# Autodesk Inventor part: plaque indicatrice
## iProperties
Author: chr
Created: 2002-03
Part Number: plaque indicatrice
Material: Par défaut
Document SubType Name: Modélisation
Designer: chr
Control State: 0
Master: False
Checked Out: False
PropertySet Name: Design Tracking Control
Shininess: 20.0
Angle Display Precision: 2
Document Length Units: 11269
Document Angle Units: 11283
Document Time Units: 11279
Document Mass Units: 11290
Document Length Units Precision: 3
Document Angle Units Precision: 2
Compacted: False
PropertySet Name: _Private Model Information
Density: 0.0
Volumn: 0.0
Area: 0.0
PropertySet Name: Model Information
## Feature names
1. Extrusion1
2. Extrusion2
3. Extrusion3
